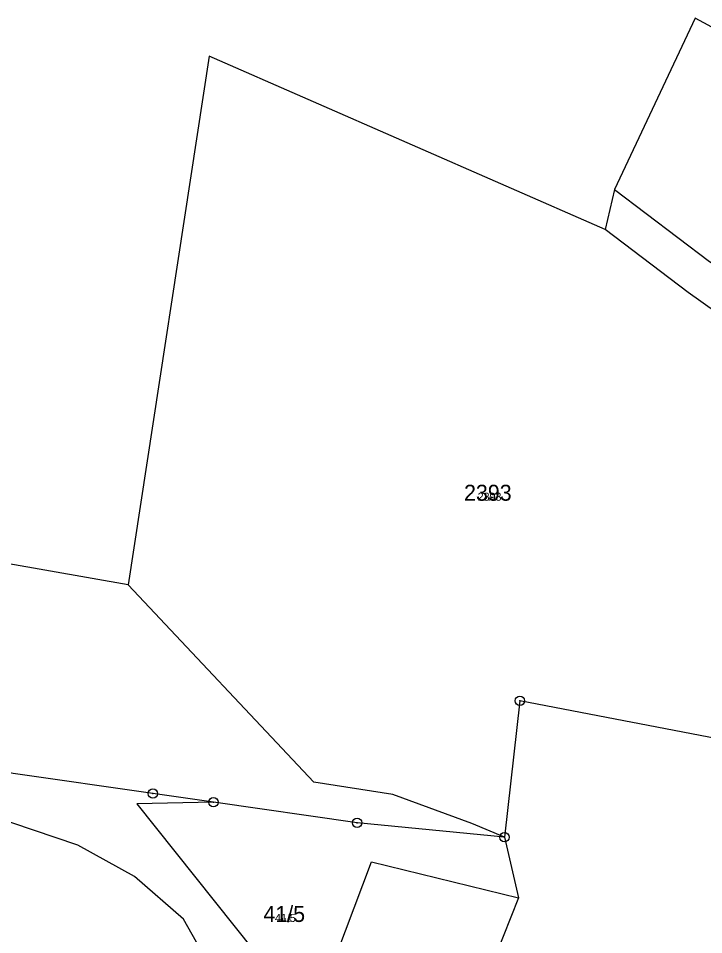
# Model space of a CAD drawing. Extents: x -744652 to -739090, y -980828 to -975855.
# Drawn here: x -742619.3 to -742546.5, y -978523.4 to -978426.1 of the extents above; entities that cross this region are included whole.
import ezdxf

# ---------------------------------------------------------------- set-up
doc = ezdxf.new("R2010")
doc.units = 0
for name, color, linetype in [('KAT_02_hranice parcel', 7, 'Continuous'), ('KAT_03_1000_čísla parcelní', 7, 'Continuous'), ('KAT_03_100_čísla parcelní', 7, 'Continuous'), ('KAT_03_250_čísla parcelní', 7, 'Continuous'), ('KAT_03_500_čísla parcelní', 7, 'Continuous'), ('KAT_11_značky bodu BP', 7, 'Continuous')]:
    doc.layers.add(name, color=color, linetype=linetype)

msp = doc.modelspace()

# ---------------------------------------------------------------- linework, layer by layer
at = {"layer": 'KAT_02_hranice parcel'}
for p, q in [((-742555.95, -978444.27), (-742556.96, -978448.53)), ((-742567.66, -978513.05), (-742566.17, -978519.49)), ((-742566.17, -978519.49), (-742571.06, -978531.84))]:
    msp.add_line(p, q, dxfattribs=at)
for points in [[(-742535.71, -978432.37), (-742547.4, -978426.09), (-742555.95, -978444.27)], [(-742556.96, -978448.53), (-742599.03, -978430.1), (-742607.63, -978486.24)], [(-742555.95, -978444.27), (-742545.87, -978451.91), (-742542.25, -978454.2), (-742525.83, -978464.15)], [(-742516.56, -978477.65), (-742548.15, -978455.2), (-742556.96, -978448.53)], [(-742607.63, -978486.24), (-742671.62, -978475), (-742720.58, -978466.15)], [(-742598.56, -978509.34), (-742604.99, -978508.42), (-742619.82, -978506.3), (-742631.87, -978503.95), (-742639.66, -978502.43), (-742639.57, -978498.96), (-742652.89, -978496.37), (-742719.91, -978481.64)], [(-742567.66, -978513.05), (-742571.11, -978511.6), (-742579.52, -978508.5), (-742587.9, -978507.2), (-742607.63, -978486.24)], [(-742542.28, -978503.12), (-742566.01, -978498.56), (-742567.66, -978513.05)], [(-742598.56, -978509.34), (-742606.7, -978509.52), (-742594.3, -978525.03), (-742592.54, -978530.97), (-742592.31, -978537.31), (-742591.99, -978547.07), (-742590.29, -978552.78), (-742587.77, -978555.92), (-742585.26, -978557.63)], [(-742567.66, -978513.05), (-742583.3, -978511.52), (-742598.56, -978509.34)], [(-742520.5, -978587.81), (-742525.48, -978582.81), (-742528, -978581.12), (-742545.21, -978576.36), (-742546.31, -978580.73), (-742562.58, -978576.21), (-742561.25, -978571.75), (-742586.77, -978562.57), (-742590.71, -978559.78), (-742594.6, -978552.66), (-742597.04, -978540.63), (-742597.4, -978531.66), (-742598.83, -978526.88), (-742601.73, -978521.76), (-742606.95, -978517.23), (-742612.97, -978513.89), (-742622.3, -978510.73)], [(-742584.33, -978538.79), (-742590.07, -978537.66), (-742581.76, -978515.66), (-742566.17, -978519.49)]]:
    msp.add_lwpolyline(points, dxfattribs=at)
at = {"layer": 'KAT_11_značky bodu BP'}
for centre, radius in [((-742566.01, -978498.56), 0.5), ((-742566.01, -978498.56), 0.0303), ((-742604.99, -978508.42), 0.5), ((-742604.99, -978508.42), 0.0303), ((-742598.56, -978509.34), 0.5), ((-742598.56, -978509.34), 0.0303), ((-742583.3, -978511.52), 0.5), ((-742583.3, -978511.52), 0.0303), ((-742567.66, -978513.05), 0.5), ((-742567.66, -978513.05), 0.0303)]:
    msp.add_circle(centre, radius, dxfattribs=at)

# ---------------------------------------------------------------- texts
at = {"layer": 'KAT_03_1000_čísla parcelní'}
for s, p in [('2393', (-742571.947, -978477.32)), ('41/5', (-742593.251, -978522.05))]:
    msp.add_text(s, height=1.7, dxfattribs=at).set_placement(p)
at = {"layer": 'KAT_03_100_čísla parcelní'}
for s, p in [('2393', (-742569.345, -978477.32)), ('41/5', (-742591.053, -978522.05))]:
    msp.add_text(s, height=0.17, dxfattribs=at).set_placement(p)
at = {"layer": 'KAT_03_250_čísla parcelní'}
for s, p in [('2393', (-742569.779, -978477.32)), ('41/5', (-742591.419, -978522.05))]:
    msp.add_text(s, height=0.425, dxfattribs=at).set_placement(p)
at = {"layer": 'KAT_03_500_čísla parcelní'}
for s, p in [('2393', (-742570.501, -978477.32)), ('41/5', (-742592.03, -978522.05))]:
    msp.add_text(s, height=0.85, dxfattribs=at).set_placement(p)

doc.saveas('drawing.dxf')
